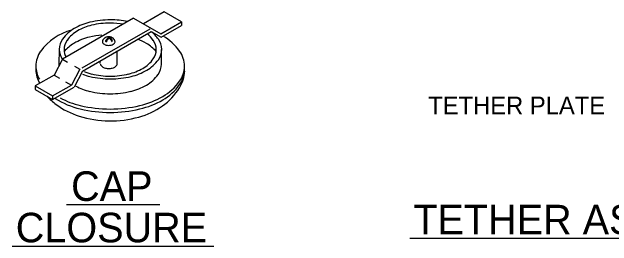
# Model space of a CAD drawing. Extents: x -1316.3 to -1303.1, y 2853.3 to 2863.3.
# Drawn here: x -1312.621 to -1310.594, y 2860.683 to 2861.475 of the extents above; entities that cross this region are included whole.
import ezdxf

# ---------------------------------------------------------------- set-up
doc = ezdxf.new("R2010")
doc.units = 0
for name, color, linetype in [('DETL-LINE', 7, 'Continuous'), ('DETL-NOTE', 7, 'Continuous'), ('DETL-TITL', 7, 'Continuous'), ('USER-BORD', 7, 'Continuous')]:
    doc.layers.add(name, color=color, linetype=linetype)

# ---------------------------------------------------------------- blocks, each defined once
blk = doc.blocks.new('DWG032')
at = {"layer": 'USER-BORD'}
for p, q in [((2.539, 1.193), (1.598, 0.65)), ((3.327, 0.738), (2.539, 1.193)), ((1.144, 0.911), (-2.1, -0.962)), ((1.144, 0.911), (2.386, 0.194)), ((2.386, 0.194), (3.327, 0.738)), ((2.393, 0.041), (3.327, 0.581)), ((3.327, 0.738), (3.327, 0.581)), ((-1.194, -1.35), (1.891, 0.432)), ((-1.189, -1.503), (1.94, 0.303)), ((1.94, 0.303), (2.393, 0.041)), ((-0.137, -0.142), (-0.099, -0.164)), ((0.148, -0.147), (0.177, -0.133)), ((-2.244, -0.513), (-2.259, -1.19)), ((2.407, -1.19), (2.407, -0.521)), ((0.398, -1.162), (0.398, -0.581)), ((-2.1, -0.962), (-2.481, -1.689)), ((-2.1, -0.962), (-1.877, -1.091)), ((-0.375, -1.162), (-0.375, -1.062)), ((-1.558, -1.275), (-1.311, -1.417)), ((-1.311, -1.417), (-1.692, -2.144)), ((-1.189, -1.503), (-1.57, -2.231)), ((-2.481, -1.689), (-3.336, -2.183)), ((-2.481, -1.689), (-2.239, -1.829)), ((-3.336, -2.183), (-3.336, -2.34)), ((-3.336, -2.183), (-2.548, -2.638)), ((-2.548, -2.638), (-1.692, -2.144)), ((-1.959, -1.99), (-1.692, -2.144)), ((-3.336, -2.34), (-2.548, -2.795)), ((-2.548, -2.795), (-1.57, -2.231)), ((-2.548, -2.638), (-2.548, -2.795))]:
    blk.add_line(p, q, dxfattribs=at)
for centre, radius, start, end in [((0.089, -3.193), 4.027, 90, 103.4495), ((0.089, -3.193), 4.027, 78.7302, 90), ((-0.228, -1.869), 2.666, 103.4495, 120), ((-0.211, -1.744), 2.399, 103.4495, 120), ((0.074, -2.936), 3.624, 90, 103.4495), ((0.074, -2.936), 3.624, 80.4918, 90), ((-1.085, -2.037), 2.47, 104.1206, 144.3429), ((-0.71, -1.035), 1.702, 120, 144.3429), ((-0.645, -0.993), 1.532, 120, 144.3429), ((0.887, -1.035), 1.702, 35.6571, 51.7971), ((-0.242, -2.546), 2.666, 103.4495, 120), ((0.074, -3.87), 4.027, 95.3793, 103.4495), ((-0.011, -0.236), 0.29, 108.0277, 128.1572), ((0.011, -0.303), 0.361, 90, 108.0277), ((-0.102, -0.314), 0.361, 71.9723, 86.3816), ((0.119, -0.261), 0.29, 110.8358, 128.1572), ((-0.111, -0.251), 0.29, 64.1002, 71.9723), ((-0.08, -0.247), 0.29, 65.789, 71.9723), ((0.011, -0.303), 0.361, 71.9723, 90), ((0.141, -0.329), 0.361, 90, 106.3394), ((0.159, -0.272), 0.29, 108.0277, 108.4934), ((-0.08, -0.247), 0.29, 51.8428, 59.4732), ((0.181, -0.339), 0.361, 92.2148, 108.0277), ((0.033, -0.236), 0.29, 51.8428, 71.9723), ((0.141, -0.329), 0.361, 89.5207, 90), ((0.793, -0.993), 1.532, 35.6571, 50.9831), ((1.232, -2.037), 2.47, 35.6571, 59.5873), ((-1.437, -0.513), 0.807, 144.3429, 180), ((-1.299, -0.523), 0.726, 144.3429, 180), ((-0.724, -1.712), 1.702, 120, 139.6035), ((-0.096, -0.166), 0.177, 152.2027, 180), ((-0.096, -0.166), 0.177, 180, 181.4993), ((-0.176, -0.166), 0.0974, 179.761, 180), ((-0.176, -0.166), 0.0974, 180, 215.6571), ((-0.088, -0.103), 0.205, 215.6571, 240), ((-0.044, -0.193), 0.236, 128.1572, 152.2027), ((0.033, -0.191), 0.177, 152.2027, 164.0832), ((0.085, -0.218), 0.236, 128.1572, 152.2027), ((0.074, -0.202), 0.177, 152.2027, 167.7033), ((0.126, -0.229), 0.236, 128.1572, 152.2027), ((0.159, -0.272), 0.29, 113.4688, 128.1572), ((-0.111, -0.251), 0.29, 51.8428, 57.6677), ((-0.078, -0.208), 0.236, 27.7973, 51.8428), ((-0.046, -0.204), 0.236, 27.7973, 51.8428), ((-0.026, -0.181), 0.177, 11.2703, 27.7973), ((0.005, -0.177), 0.177, 14.3343, 27.7973), ((0.105, -0.103), 0.205, 300, 324.3429), ((0.067, -0.193), 0.236, 27.7973, 51.8428), ((0.19, -0.145), 0.113, 316.3178, 343.7669), ((0.119, -0.166), 0.177, 0, 27.7973), ((0.119, -0.166), 0.177, 357.2982, 0), ((0.391, -2.546), 2.666, 60, 69.4275), ((0.873, -1.712), 1.702, 40.4218, 60), ((1.447, -0.523), 0.726, 0, 35.6571), ((1.614, -0.513), 0.807, 0, 35.6571), ((-1.437, -0.513), 0.807, 180, 214.3525), ((-1.299, -0.523), 0.726, 180, 208.3649), ((-0.03, -0.003), 0.322, 240, 256.5505), ((0.008, 0.157), 0.486, 256.5505, 270), ((0.008, 0.157), 0.486, 270, 283.4495), ((0.046, -0.003), 0.322, 283.4495, 300), ((1.447, -0.523), 0.726, 324.3429, 0), ((1.614, -0.513), 0.807, 324.3429, 0), ((-2.141, -1.28), 1.171, 144.3429, 180), ((2.288, -1.28), 1.171, 0, 35.6571), ((0.793, -0.054), 1.532, 300, 324.3429), ((0.887, 0.009), 1.702, 300, 324.3429), ((-2.141, -1.28), 1.171, 180, 210.3794), ((-2.141, -1.437), 1.171, 176.1699, 180), ((-1.451, -1.19), 0.807, 177.5501, 180), ((-1.451, -1.19), 0.807, 180, 184.9062), ((-0.241, -1.162), 0.134, 189.3704, 215.6571), ((-0.121, -1.076), 0.282, 215.6571, 240), ((-0.041, -0.937), 0.442, 240, 256.5505), ((0.064, -0.937), 0.442, 283.4495, 300), ((0.144, -1.076), 0.282, 300, 324.3429), ((0.264, -1.162), 0.134, 324.3429, 357.4835), ((1.6, -1.19), 0.807, 324.3429, 0), ((2.288, -1.28), 1.171, 324.3429, 0), ((2.288, -1.437), 1.171, 0, 3.8301), ((-2.141, -1.437), 1.171, 180, 212.3663), ((-0.211, 0.697), 2.399, 247.7886, 256.5505), ((0.074, 1.889), 3.624, 256.5505, 270), ((0.011, -0.718), 0.667, 256.5505, 270), ((0.011, -0.718), 0.667, 270, 283.4495), ((0.074, 1.889), 3.624, 270, 283.4495), ((0.359, 0.697), 2.399, 283.4495, 300), ((0.405, 0.843), 2.666, 283.4495, 300), ((1.704, -1.35), 1.779, 329.0647, 354.9981), ((2.288, -1.437), 1.171, 324.3429, 0), ((-0.228, 0.843), 2.666, 249.0311, 256.5505), ((0.089, 2.167), 4.027, 256.5505, 270), ((0.089, 2.167), 4.027, 270, 283.4495), ((0.873, -0.668), 1.702, 300, 324.3429), ((0.391, 0.166), 2.666, 283.4495, 300), ((1.232, -0.523), 2.47, 300, 324.3429), ((1.232, -0.68), 2.47, 300, 324.3429), ((-0.242, 0.166), 2.666, 241.9837, 256.5505), ((0.074, 1.49), 4.027, 256.5505, 270), ((0.074, 1.49), 4.027, 270, 283.4495), ((0.92, -0.88), 2.693, 304.7146, 329.0647), ((-0.792, -0.854), 2.693, 221.8425, 233.5698), ((-0.386, 0.688), 3.869, 241.9608, 256.5505), ((0.533, 0.688), 3.869, 283.4495, 300), ((-0.386, 0.532), 3.869, 238.0352, 256.5505), ((0.533, 0.532), 3.869, 283.4495, 300), ((-0.263, -0.139), 3.583, 233.5698, 252.6405), ((0.074, 2.61), 5.844, 256.5505, 270), ((0.074, 2.453), 5.844, 256.5505, 270), ((0.074, 2.61), 5.844, 270, 283.4495), ((0.074, 2.453), 5.844, 270, 283.4495), ((0.413, -0.149), 3.583, 285.6439, 304.7146), ((0.092, 0.998), 4.774, 252.6405, 269.1422), ((0.092, 0.998), 4.774, 269.1422, 285.6439)]:
    blk.add_arc(centre, radius, start, end, dxfattribs=at)

msp = doc.modelspace()

# ---------------------------------------------------------------- linework, layer by layer
at = {"layer": 'DETL-TITL'}
for p, q in [((-1312.4361, 2860.8232), (-1312.1211, 2860.8232)), ((-1311.2768, 2860.71), (-1309.9072, 2860.71)), ((-1312.6206, 2860.6831), (-1311.9386, 2860.6831))]:
    msp.add_line(p, q, dxfattribs=at)

# ---------------------------------------------------------------- block references
at = {"layer": 'DETL-LINE', "xscale": 0.07412006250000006, "yscale": 0.07412006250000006}
msp.add_blockref('DWG032', (-1312.2946, 2861.3861), dxfattribs=at)

# ---------------------------------------------------------------- texts
at = {"layer": 'DETL-NOTE'}
msp.add_text('TETHER PLATE', height=0.06, dxfattribs=at).set_placement((-1311.215, 2861.1285))
at = {"layer": 'DETL-TITL'}
for s, p in [('CAP', (-1312.421, 2860.8357)), ('TETHER ASSEMBLY', (-1311.2655, 2860.7225)), ('CLOSURE', (-1312.608, 2860.6956))]:
    msp.add_text(s, height=0.1, dxfattribs=at).set_placement(p)

doc.saveas('drawing.dxf')
